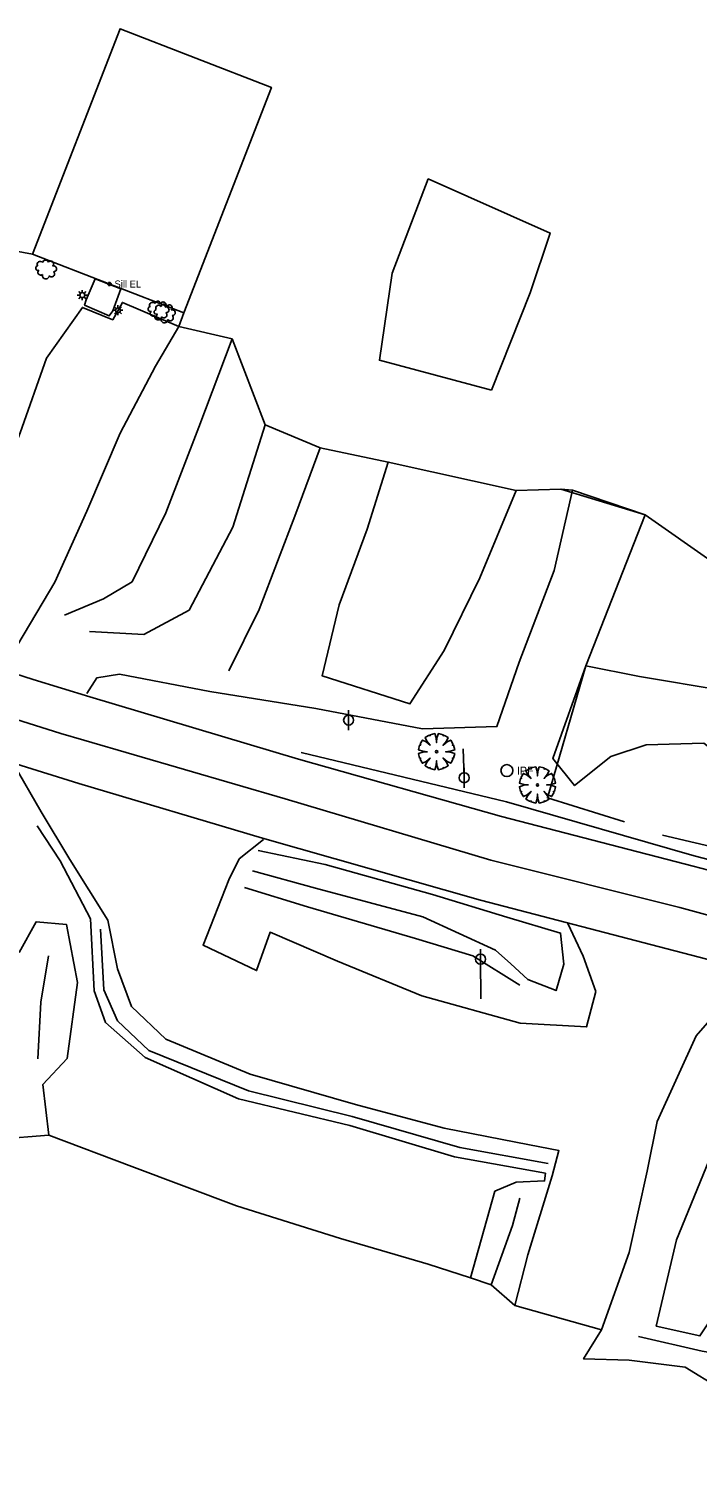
# Model space of a CAD drawing. Extents: x 1158469 to 1165378, y 609843 to 611748.
# Drawn here: x 1158909.5 to 1159076.5, y 611195.6 to 611554.7 of the extents above; entities that cross this region are included whole.
import ezdxf

# ---------------------------------------------------------------- set-up
doc = ezdxf.new("R2010")
doc.units = 0
for name, color, linetype in [('Exterior Boundary', 7, 'Continuous'), ('S_Buildings', 7, 'Continuous'), ('S_Buildings_SillElevation', 7, 'Continuous'), ('S_Buildings_Steps_Brick', 7, 'Continuous'), ('S_Fencing_PostAndRail', 7, 'Continuous'), ('S_Ground_Elevation', 7, 'Continuous'), ('S_Property_IronPipeFound', 7, 'Continuous'), ('S_Property_Leachfield', 7, 'Continuous'), ('S_Property_Light', 7, 'Continuous'), ('S_Roadway_Centerline', 7, 'Continuous'), ('S_Roadway_Drive_Gravel', 7, 'Continuous'), ('S_Roadway_Edge_Pavement', 7, 'Continuous'), ('S_Roadway_Edge_Shoulder', 7, 'Continuous'), ('S_Trees_Bush', 7, 'Continuous'), ('S_Trees_Decid_Pay', 7, 'Continuous'), ('S_Utilities_GuyWire3', 7, 'Continuous'), ('S_Utilities_Pole_Power', 7, 'Continuous')]:
    doc.layers.add(name, color=color, linetype=linetype)

msp = doc.modelspace()

# ---------------------------------------------------------------- linework, layer by layer
at = {"layer": 'Exterior Boundary'}
for points in [[(1159080.75, 611421.12), (1159063.46, 611433.13), (1159045.37, 611439.36), (1159042.41, 611439.62), (1159031.27, 611439.21), (1158999.33, 611446.33), (1158982.35, 611449.92), (1158968.57, 611455.64), (1158960.31, 611477.14), (1158947.06, 611480.27), (1158948.27, 611483.68), (1158910.45, 611498.3), (1158890.25, 611502.09)], [(1158889.33, 611276.16), (1158914.58, 611278.16), (1158935.32, 611270.3), (1158961.43, 611260.45), (1158987.42, 611252.32), (1159009.29, 611245.9), (1159019.83, 611242.45), (1159025.05, 611240.7), (1159030.92, 611235.57), (1159052.56, 611229.45), (1159048.11, 611222.2), (1159059.48, 611221.91), (1159073.44, 611220.14), (1159081.84, 611214.97)]]:
    msp.add_lwpolyline(points, dxfattribs=at)
at = {"layer": 'S_Buildings'}
msp.add_lwpolyline([(1158910.45, 611498.3), (1158948.27, 611483.68), (1158970.14, 611539.97), (1158932.35, 611554.66)], close=True, dxfattribs=at)
at = {"layer": 'S_Buildings_SillElevation'}
msp.add_line((1158929.7, 611490.86), (1158929.7, 611491.25), dxfattribs=at)
msp.add_lwpolyline([(1158930.1, 611491.02), (1158929.87, 611491.25), (1158929.54, 611491.25), (1158929.31, 611491.02), (1158929.31, 611490.7), (1158929.54, 611490.47), (1158929.87, 611490.47), (1158930.1, 611490.7)], close=True, dxfattribs=at)
at = {"layer": 'S_Buildings_Steps_Brick'}
msp.add_lwpolyline([(1158926.15, 611492.17), (1158923.88, 611486.86), (1158923.48, 611485.59), (1158929.66, 611482.87), (1158930.58, 611484.12), (1158932.57, 611489.66)], close=True, dxfattribs=at)
at = {"layer": 'S_Fencing_PostAndRail'}
for points in [[(1159058.34, 611356.42), (1159039.07, 611362.42), (1159048.64, 611395.43), (1159063.46, 611433.13)], [(1159224.05, 611398.88), (1159216.11, 611369.59), (1159204.94, 611321.1), (1159165.67, 611330.11), (1159067.84, 611353.1)]]:
    msp.add_lwpolyline(points, dxfattribs=at)
at = {"layer": 'S_Ground_Elevation'}
for points in [[(1158904.32, 611395.15), (1158906.79, 611400.72), (1158916.02, 611416.31), (1158924.09, 611434.05), (1158932.36, 611453.59), (1158941.22, 611470.3), (1158947.06, 611480.27), (1158932.94, 611486.27), (1158930.52, 611481.92), (1158922.93, 611484.99), (1158913.99, 611472.35), (1158907.43, 611453.65), (1158900.18, 611434.86), (1158890.38, 611416.5), (1158886.53, 611410.08), (1158882.51, 611403.01)], [(1158959.48, 611394.21), (1158967.05, 611409.49), (1158976.23, 611433.46), (1158982.35, 611449.92), (1158999.33, 611446.33), (1158994.04, 611429.54), (1158987.07, 611410.71), (1158982.82, 611392.89), (1159004.72, 611385.91), (1159013.28, 611399.22), (1159022.2, 611417.4), (1159031.27, 611439.21)], [(1159094.2, 611363.7), (1159078.09, 611376.08), (1159063.74, 611375.67), (1159054.93, 611372.77), (1159045.87, 611365.49), (1159040.44, 611372.25), (1159048.64, 611395.43), (1159062.07, 611392.76), (1159082.97, 611389.29), (1159101.7, 611384.1), (1159115.73, 611395.93), (1159100.36, 611410.62), (1159080.75, 611421.12), (1159063.46, 611433.13), (1159042.41, 611439.62)], [(1158907.13, 611323.79), (1158911.37, 611331.43), (1158918.96, 611330.8), (1158921.74, 611316.32), (1158919.12, 611297.32), (1158913.08, 611290.78), (1158914.58, 611278.16), (1158935.32, 611270.3), (1158961.43, 611260.45), (1158987.42, 611252.32), (1159009.29, 611245.9), (1159019.83, 611242.45), (1159025.96, 611264.09), (1159031.3, 611266.36), (1159038.34, 611266.68), (1159038.58, 611268.6), (1159015.89, 611272.72), (1158989.75, 611280.55), (1158961.95, 611287.23), (1158938.63, 611297.56), (1158928.74, 611306.26), (1158925.87, 611314.22), (1158924.96, 611332.21), (1158917.4, 611346.65), (1158911.63, 611355.41)], [(1158966.83, 611349.23), (1158983.57, 611345.76), (1159010.34, 611338.31), (1159028.97, 611332.57), (1159042.34, 611328.62), (1159043.16, 611320.83), (1159041.25, 611314.24), (1159034.17, 611317.06), (1159029.91, 611320.91)], [(1158965.45, 611344.23), (1158981.16, 611339.83), (1159007.98, 611332.69), (1159026.1, 611324.36), (1159029.91, 611320.91)], [(1158963.41, 611340.05), (1158979.18, 611335.23), (1159006.11, 611327.27), (1159020.48, 611322.98), (1159032.2, 611315.62)], [(1159039.27, 611271.02), (1159017.22, 611275.02), (1158990.33, 611282.81), (1158964.43, 611289.18), (1158939.51, 611299.26), (1158931.74, 611306.67), (1158928.3, 611314.46), (1158927.49, 611329.6)], [(1158911.83, 611297.22), (1158912.57, 611311.33), (1158914.44, 611322.96)], [(1159088.54, 611294.39), (1159078.59, 611269.87), (1159071.32, 611251.93), (1159066.24, 611230.4), (1159077.15, 611227.97), (1159086.5, 611242.08), (1159093.61, 611260.5), (1159101.74, 611285.9)], [(1159025.05, 611240.7), (1159030.32, 611255.54), (1159032.21, 611262.34)], [(1159061.85, 611227.81), (1159077.75, 611224.18), (1159091.39, 611221.78), (1159103.11, 611221.71), (1159116.5, 611222.65), (1159125.25, 611217.59), (1159134.28, 611212.15), (1159131.92, 611195.62), (1159120.81, 611201.75), (1159107.63, 611209.01), (1159093.36, 611210.68), (1159081.84, 611214.97), (1159073.44, 611220.14), (1159059.48, 611221.91), (1159048.11, 611222.2)]]:
    msp.add_lwpolyline(points, dxfattribs=at)
at = {"layer": 'S_Property_IronPipeFound'}
msp.add_circle((1159028.95, 611369.23), 1.5, dxfattribs=at)
at = {"layer": 'S_Property_Leachfield'}
msp.add_lwpolyline([(1159025.12, 611464.36), (1159034.78, 611488.63), (1159039.76, 611503.58), (1159009.3, 611517.14), (1159000.31, 611493.57), (1158997.13, 611471.8)], close=True, dxfattribs=at)
at = {"layer": 'S_Property_Light'}
for p, q in [((1158922.29, 611488.07), (1158921.67, 611488.07)), ((1158922.48, 611488.51), (1158922.03, 611488.96)), ((1158922.92, 611488.7), (1158922.92, 611489.32)), ((1158923.36, 611488.51), (1158923.8, 611488.96)), ((1158923.54, 611488.07), (1158924.17, 611488.07)), ((1158922.48, 611487.63), (1158922.03, 611487.19)), ((1158922.92, 611487.45), (1158922.92, 611486.82)), ((1158923.36, 611487.63), (1158923.8, 611487.19)), ((1158931.21, 611484.28), (1158930.58, 611484.28)), ((1158931.39, 611484.73), (1158930.95, 611485.17)), ((1158931.83, 611484.91), (1158931.83, 611485.53)), ((1158932.28, 611484.73), (1158932.72, 611485.17)), ((1158932.46, 611484.28), (1158933.08, 611484.28)), ((1158931.39, 611483.84), (1158930.95, 611483.4)), ((1158931.83, 611483.66), (1158931.83, 611483.03)), ((1158932.28, 611483.84), (1158932.72, 611483.4))]:
    msp.add_line(p, q, dxfattribs=at)
for centre in [(1158922.92, 611488.07), (1158931.83, 611484.28)]:
    msp.add_circle(centre, 0.625, dxfattribs=at)
at = {"layer": 'S_Roadway_Centerline'}
msp.add_lwpolyline([(1159331.81, 611277.28), (1159274.84, 611288.49), (1159224.73, 611298.33), (1159175.26, 611310.41), (1159123.67, 611320.98), (1159072.1, 611335.03), (1159024.95, 611346.83), (1158973.61, 611362.21), (1158923.32, 611376.81), (1158917.59, 611378.51), (1158906.21, 611382.09)], dxfattribs=at)
at = {"layer": 'S_Roadway_Drive_Gravel'}
for points in [[(1158960.31, 611477.14), (1158952.06, 611455.11), (1158943.8, 611433.63), (1158935.37, 611416.43), (1158928.22, 611412.16), (1158918.44, 611408.08)], [(1158924.7, 611404.02), (1158938.32, 611403.25), (1158949.64, 611409.36), (1158960.5, 611430.12), (1158968.57, 611455.64)], [(1159045.37, 611439.36), (1159040.76, 611419.29), (1159031.98, 611396.35), (1159026.47, 611380.25), (1159007.87, 611379.72), (1158981.21, 611384.77), (1158954.75, 611389.05), (1158932.22, 611393.33), (1158926.52, 611392.39), (1158924.04, 611388.47)], [(1158905.77, 611370.97), (1158912.67, 611358.92), (1158919.77, 611347.01), (1158929.28, 611331.83), (1158931.7, 611319.68), (1158935.24, 611310.27), (1158943.82, 611302.1), (1158964.81, 611293.34), (1158991.16, 611285.77), (1159013.31, 611279.88), (1159034.57, 611275.74), (1159041.92, 611274.25), (1159040.27, 611267.98), (1159034.17, 611248.21), (1159030.92, 611235.57)], [(1159044.16, 611330.99), (1159048, 611322.82), (1159051.19, 611314.07), (1159048.83, 611305.18), (1159032.3, 611306.12), (1159007.72, 611312.97), (1158986.67, 611321.63), (1158969.8, 611328.84), (1158966.43, 611319.24), (1158953.1, 611325.58), (1158959.47, 611341.9), (1158962.06, 611347.18), (1158968.2, 611352)], [(1159052.56, 611229.45), (1159059.49, 611248.82), (1159063.99, 611269.11), (1159066.47, 611281.51), (1159076.22, 611302.93), (1159084.19, 611312.09), (1159094.89, 611317.34)]]:
    msp.add_lwpolyline(points, dxfattribs=at)
at = {"layer": 'S_Roadway_Edge_Pavement'}
for points in [[(1159333.57, 611289.26), (1159323.43, 611291.71), (1159276.2, 611299.9), (1159226.25, 611309.31), (1159178.31, 611320.23), (1159127.18, 611331.87), (1159075.46, 611345.32), (1159027.63, 611357.79), (1158976.91, 611372.12), (1158924.82, 611387.65), (1158910.66, 611392.01), (1158903.63, 611394.28)], [(1159331.91, 611265.57), (1159323.93, 611267.01), (1159320.48, 611267.38), (1159273.69, 611277.35), (1159249.33, 611282.09), (1159221.46, 611287.37), (1159172.87, 611299.32), (1159121.37, 611311.03), (1159070.91, 611324.22), (1159022.32, 611336.86), (1158967.91, 611352.37), (1158922.03, 611366.05), (1158906.33, 611370.96)]]:
    msp.add_lwpolyline(points, dxfattribs=at)
at = {"layer": 'S_Roadway_Edge_Shoulder'}
msp.add_lwpolyline([(1159227.63, 611312.2), (1159178.87, 611322.51), (1159127.52, 611334.43), (1159075.72, 611347.92), (1159028.86, 611361.42), (1158977.58, 611373.79)], dxfattribs=at)
at = {"layer": 'S_Trees_Bush'}
for centre, radius, start, end in [((1158911.83, 611494.84), 0.576, 95.1875, 295.4615), ((1158912.38, 611495.81), 0.717, 33.6405, 213.5909), ((1158913.73, 611496.04), 0.776, 19.7277, 168.0032), ((1158915.05, 611495.9), 0.715, 304.7168, 145.2832), ((1158915.78, 611494.65), 0.733, 268.122, 116.0172), ((1158912.53, 611493.77), 0.706, 129.1555, 309.4105), ((1158913.8, 611492.98), 0.862, 163.7427, 356.276), ((1158915.26, 611493.37), 0.742, 216.9809, 47.4965), ((1158939.89, 611484.59), 0.576, 95.1875, 295.4615), ((1158940.43, 611485.56), 0.717, 33.6405, 213.5909), ((1158941.45, 611483.87), 0.576, 95.1875, 295.4615), ((1158941.79, 611485.79), 0.776, 19.7277, 168.0032), ((1158942, 611484.84), 0.717, 33.6405, 213.5909), ((1158943.11, 611485.65), 0.715, 304.7168, 145.2832), ((1158943.35, 611485.07), 0.776, 19.7277, 168.0032), ((1158943.84, 611484.4), 0.733, 268.122, 116.0172), ((1158944.67, 611484.93), 0.715, 304.7168, 145.2832), ((1158945.4, 611483.68), 0.733, 268.122, 116.0172), ((1158940.58, 611483.52), 0.706, 129.1555, 309.4105), ((1158941.86, 611482.73), 0.862, 163.7427, 356.276), ((1158942.15, 611482.8), 0.706, 129.1555, 309.4105), ((1158943.42, 611482.01), 0.862, 163.7427, 356.276), ((1158943.31, 611483.12), 0.742, 216.9809, 47.4965), ((1158944.87, 611482.4), 0.742, 216.9809, 47.4965)]:
    msp.add_arc(centre, radius, start, end, dxfattribs=at)
at = {"layer": 'S_Trees_Decid_Pay'}
for points in [[(1159009.14, 611373.97), (1159007.96, 611374.06), (1159006.88, 611374.42), (1159007.15, 611375.59), (1159007.42, 611375.59), (1159007.33, 611375.96), (1159007.87, 611376.86), (1159008.78, 611376.41), (1159009.77, 611375.59), (1159008.96, 611376.59), (1159008.51, 611377.49), (1159009.41, 611378.03), (1159009.77, 611377.94), (1159009.77, 611378.21), (1159010.94, 611378.48), (1159011.3, 611377.4), (1159011.39, 611376.23), (1159011.48, 611377.4), (1159011.85, 611378.48), (1159013.02, 611378.21), (1159013.02, 611377.94), (1159013.38, 611378.03), (1159014.28, 611377.49), (1159013.83, 611376.59), (1159013.02, 611375.59), (1159014.01, 611376.41), (1159014.91, 611376.86), (1159015.45, 611375.96), (1159015.36, 611375.59), (1159015.63, 611375.59), (1159015.91, 611374.42), (1159014.82, 611374.06), (1159013.65, 611373.97), (1159014.82, 611373.88), (1159015.91, 611373.52), (1159015.63, 611372.35), (1159015.36, 611372.35), (1159015.45, 611371.99), (1159014.91, 611371.08), (1159014.01, 611371.54), (1159013.02, 611372.35), (1159013.83, 611371.35), (1159014.28, 611370.45), (1159013.38, 611369.91), (1159013.02, 611370), (1159013.02, 611369.73), (1159011.85, 611369.46), (1159011.48, 611370.54), (1159011.39, 611371.72), (1159011.3, 611370.54), (1159010.94, 611369.46), (1159009.77, 611369.73), (1159009.77, 611370), (1159009.41, 611369.91), (1159008.51, 611370.45), (1159008.96, 611371.35), (1159009.77, 611372.35), (1159008.78, 611371.54), (1159007.87, 611371.08), (1159007.33, 611371.99), (1159007.42, 611372.35), (1159007.15, 611372.35), (1159006.88, 611373.52), (1159007.96, 611373.88), (1159009.14, 611373.97)], [(1159034.34, 611365.65), (1159033.16, 611365.74), (1159032.08, 611366.1), (1159032.35, 611367.27), (1159032.62, 611367.27), (1159032.53, 611367.63), (1159033.07, 611368.54), (1159033.98, 611368.08), (1159034.97, 611367.27), (1159034.16, 611368.26), (1159033.71, 611369.17), (1159034.61, 611369.71), (1159034.97, 611369.62), (1159034.97, 611369.89), (1159036.14, 611370.16), (1159036.5, 611369.08), (1159036.59, 611367.9), (1159036.68, 611369.08), (1159037.04, 611370.16), (1159038.22, 611369.89), (1159038.22, 611369.62), (1159038.58, 611369.71), (1159039.48, 611369.17), (1159039.03, 611368.26), (1159038.22, 611367.27), (1159039.21, 611368.08), (1159040.11, 611368.54), (1159040.65, 611367.63), (1159040.56, 611367.27), (1159040.83, 611367.27), (1159041.11, 611366.1), (1159040.02, 611365.74), (1159038.85, 611365.65), (1159040.02, 611365.56), (1159041.11, 611365.2), (1159040.83, 611364.02), (1159040.56, 611364.02), (1159040.65, 611363.66), (1159040.11, 611362.76), (1159039.21, 611363.21), (1159038.22, 611364.02), (1159039.03, 611363.03), (1159039.48, 611362.13), (1159038.58, 611361.59), (1159038.22, 611361.68), (1159038.22, 611361.41), (1159037.04, 611361.14), (1159036.68, 611362.22), (1159036.59, 611363.39), (1159036.5, 611362.22), (1159036.14, 611361.14), (1159034.97, 611361.41), (1159034.97, 611361.68), (1159034.61, 611361.59), (1159033.71, 611362.13), (1159034.16, 611363.03), (1159034.97, 611364.02), (1159033.98, 611363.21), (1159033.07, 611362.76), (1159032.53, 611363.66), (1159032.62, 611364.02), (1159032.35, 611364.02), (1159032.08, 611365.2), (1159033.16, 611365.56), (1159034.34, 611365.65)]]:
    msp.add_lwpolyline(points, dxfattribs=at)
for centre in [(1159011.39, 611373.97), (1159036.59, 611365.65)]:
    msp.add_circle(centre, 0.283, dxfattribs=at)
at = {"layer": 'S_Utilities_GuyWire3'}
for points in [[(1159018.28, 611367.46), (1159018.05, 611374.65)], [(1159022.37, 611322.11), (1159022.42, 611312.16)]]:
    msp.add_lwpolyline(points, dxfattribs=at)
at = {"layer": 'S_Utilities_Pole_Power'}
for p, q in [((1158989.43, 611384.37), (1158989.43, 611379.37)), ((1159018.28, 611369.96), (1159018.28, 611364.96)), ((1159022.37, 611324.61), (1159022.37, 611319.61))]:
    msp.add_line(p, q, dxfattribs=at)
for centre in [(1158989.43, 611381.87), (1159018.28, 611367.46), (1159022.37, 611322.11)]:
    msp.add_circle(centre, 1.25, dxfattribs=at)

# ---------------------------------------------------------------- texts
at = {"layer": 'S_Buildings_SillElevation'}
msp.add_text('Sill EL', height=1.75, dxfattribs=at).set_placement((1158930.97, 611489.98))
at = {"layer": 'S_Property_IronPipeFound'}
msp.add_text('IPF', height=2, dxfattribs=at).set_placement((1159031.45, 611368.23))

doc.saveas('drawing.dxf')
